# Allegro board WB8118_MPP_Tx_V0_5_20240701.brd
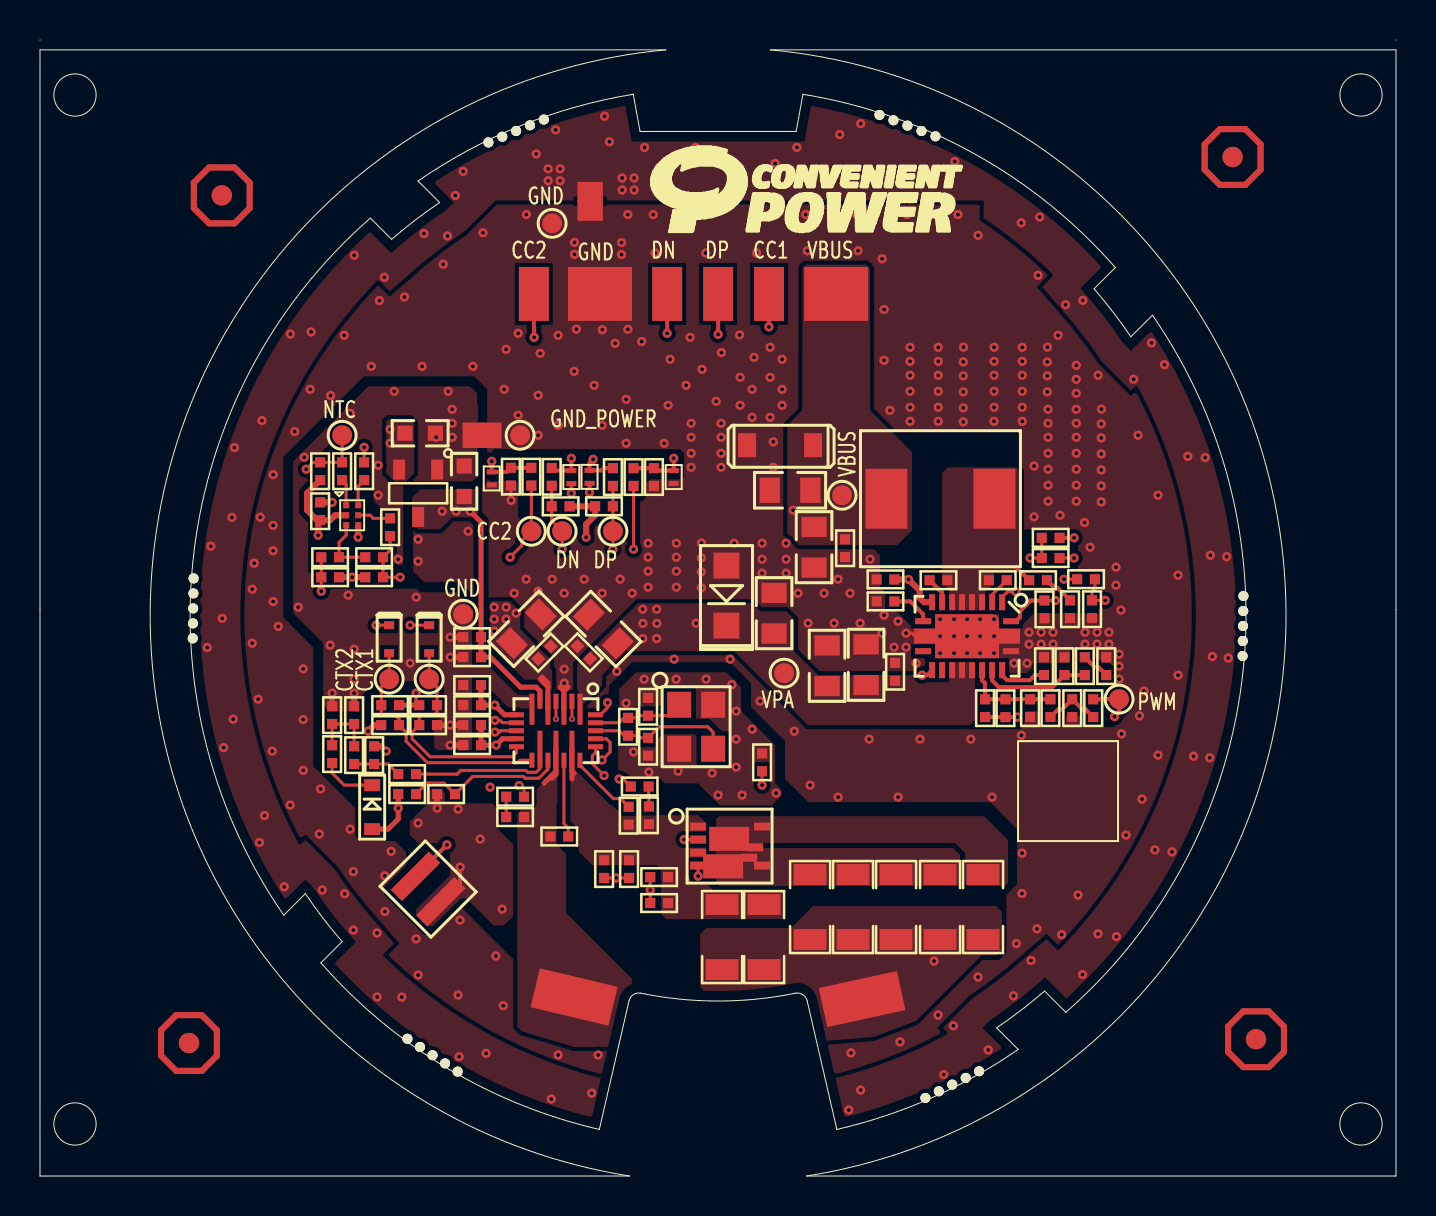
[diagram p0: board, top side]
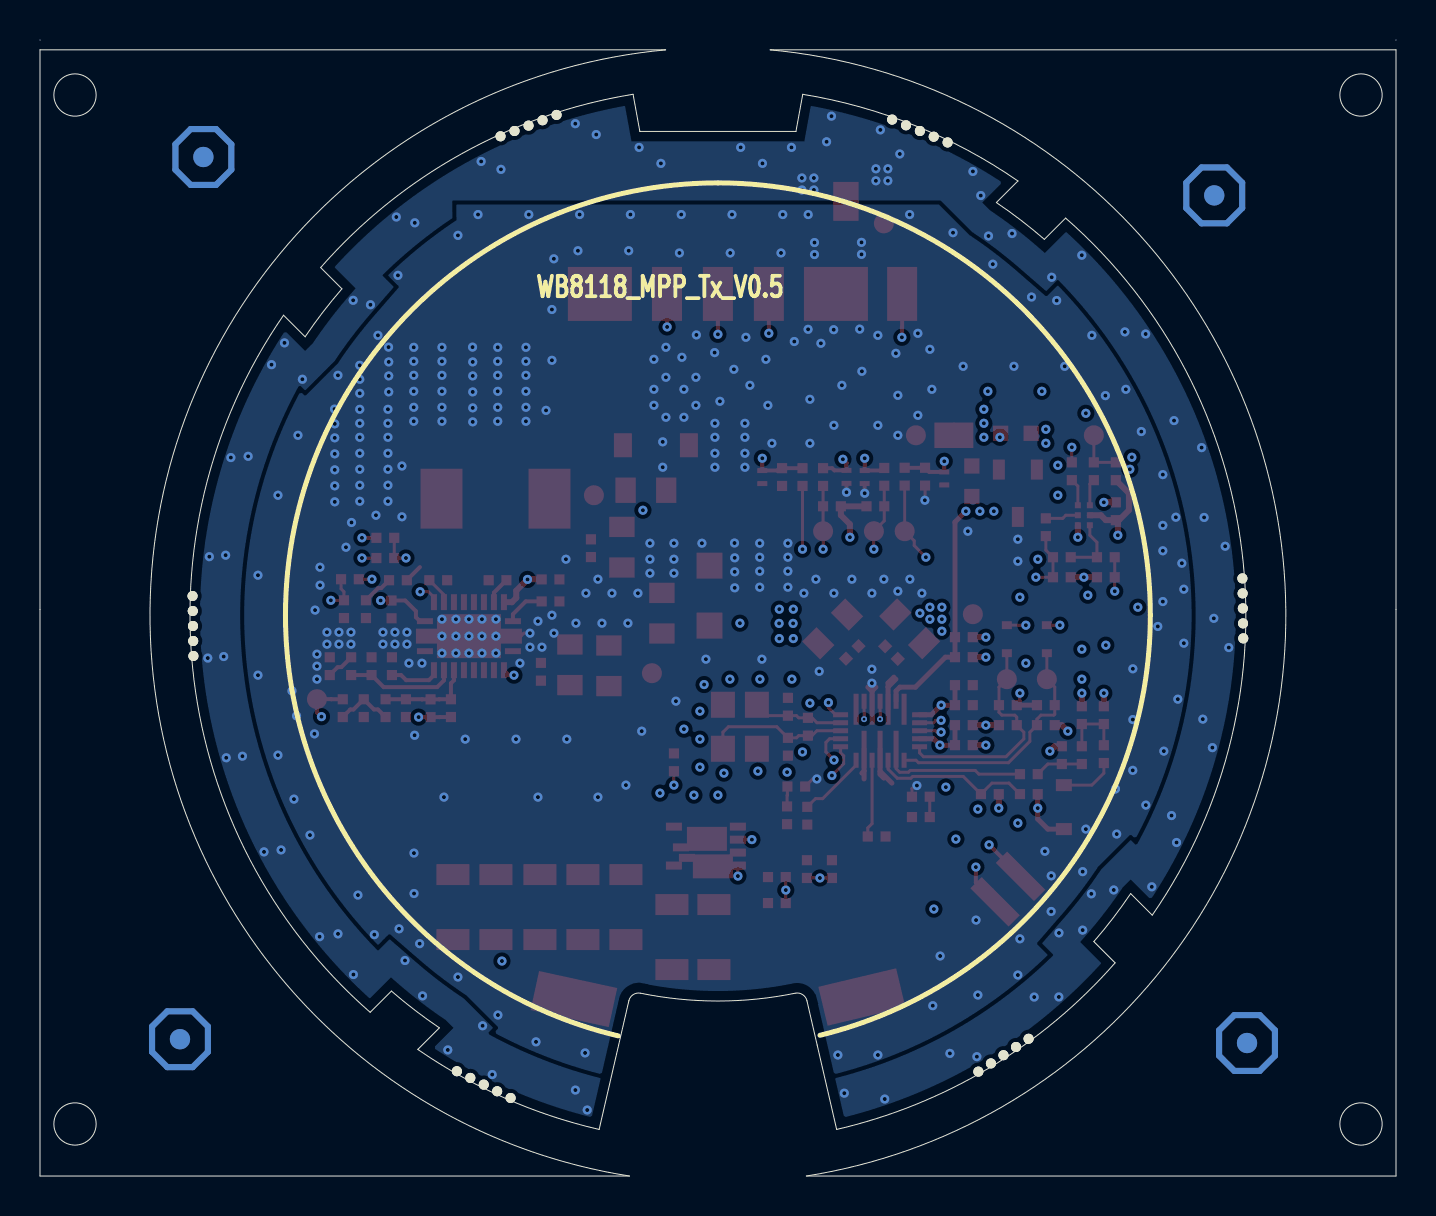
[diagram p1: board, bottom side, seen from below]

Outline 67.81 x 56.83 mm; copper layers: TOP, L2_GND, L3_PWR, BOTTOM. Coordinates in mm from the lower left corner of the outline.
Outline path: circle c1.75,54.07 r1.06 ; circle c1.75,2.6 r1.06 ; circle c66.06,54.07 r1.06 ; circle c66.06,2.6 r1.06 ; 0,56.82 0,56.83 ; 67.81,56.83 67.81,56.82 ; 0,56.33 0,0 29.49,0 arc(5.52,28.97) 31.3,56.33 0,56.33 ; 12.19,13.05 13.27,14.13 arc(14.15,12.9) 15.11,11.73 14.05,10.66 arc(20.35,5.4) 27.97,2.33 28.94,6.55 29.46,8.77 arc(29.67,9.08) 30.04,9.14 arc(33.91,8.75) 37.78,9.14 arc(38.15,9.08) 38.36,8.77 39.85,2.33 arc(44.57,3.9) 48.92,6.33 47.84,7.41 arc(49.06,8.3) 50.24,9.25 51.3,8.19 arc(60.11,24.8) 55.63,43.06 54.55,41.98 arc(53.67,43.21) 52.71,44.38 53.77,45.44 arc(46.72,51.14) 38.15,54.11 37.81,52.25 30.01,52.25 29.67,54.11 arc(24.04,52.54) 18.9,49.77 19.98,48.69 arc(18.76,47.81) 17.58,46.85 16.52,47.92 arc(7.71,31.31) 12.19,13.05 ; 36.52,56.33 arc(62.3,28.97) 38.33,0 67.81,0 67.81,56.33 36.52,56.33

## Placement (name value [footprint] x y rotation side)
C1  1000pF  [C0402]  51.51 28.35 90 top
C2  0.1uF  [C0402]  44.93 29.8 180 top
C5  0.1uF  [C0402]  40.26 31.4 270 top
C6  22uF  [C0805]  38.71 31.45 270 top
C7  22uF  [C0805]  37.51 34.3 180 top
C8  0.1uF  [C0402]  42.76 25.22 90 top
C10  22uF  [C0805]  41.31 25.57 90 top
C11  22uF  [C0805]  39.36 25.52 90 top
C12  22uF  [C0805]  36.71 28.15 90 top
C14  33pF  [C0402]  47.26 23.4 90 top
C15  1uF  [C0402]  50.23 28.34 270 top
C17  0.01uF  [C0402]  51.62 23.4 90 top
C21  4700pF  [C0402]  29.99 19.48 180 top
C22  0.1uF  [C1206]  38.51 13.45 270 top
C23  22uF  [C0805]  24.32 27.37 45 top
C24  0.1uF  [C1206]  40.66 13.45 270 top
C25  0.1uF  [C0402]  29.44 18.02 270 top
C26  0.022uF  [C0402]  30.96 14.95 180 top
C27  4700pF  [C0402]  23.76 18.97 180 top
C28  0.1uF  [C1206]  42.81 13.45 270 top
C29  2.2uF  [C0402]  21.61 25.95 180 top
C30  0.1uF  [C0402]  21.61 26.95 180 top
C32  0.1uF  [C1206]  45.01 13.45 270 top
C33  0.1uF  [C0402]  27.19 26.19 135 top
C34  22uF  [C0805]  28.17 27.36 135 top
C35  0.1uF  [C0402]  25.23 26.18 45 top
C36  0.1uF  [C0402]  25.97 16.98 180 top
C37  15pF  [C0402]  30.41 21.47 90 top
C38  0.047uF  [C1206]  47.16 13.45 90 top
C39  0.022uF  [C0402]  28.21 15.35 270 top
C40  0.022uF  [C0402]  18.36 20.1 180 top
C41  15pF  [C0402]  30.41 23.47 270 top
C42  2.2uF  [C0402]  21.61 23.55 180 top
C43  0.1uF  [C0402]  21.61 24.55 180 top
C44  2.2uF  [C0402]  21.61 22.55 180 top
C45  0.1uF  [C0402]  21.61 21.55 180 top
C46  0.01uF  [C0402]  16.71 21.05 90 top
C47  0.01uF  [C0402]  15.71 23.05 90 top
C48  0.022uF  [C1206]  36.21 11.95 270 top
C49  0.033uF  [C1206]  34.11 11.95 270 top
C51  0.01uF  [C0402]  42.28 28.74 0 top
C52  0.01uF  [C0402]  53.32 25.5 270 top
C54  1uF  [C0402]  42.28 29.84 180 top
C55  33pF  [C0402]  51.23 25.5 90 top
C56  10uF  [C0603]  21.21 34.75 90 top
C57  0.1uF  [C0402]  14.01 33.25 90 top
C58  10uF  [C0603]  19.01 37.15 0 top
D1  -  [SMF12CA]  37.01 36.55 180 top
D2  5V  [SMD-2-X0_6Y0_55-0_85-B]  31.69 34.96 90 top
D3  5V  [SMD-2-X0_6Y0_55-0_85-B]  22.59 34.89 90 top
D4  5V  [SMD-2-X0_6Y0_55-0_85-B]  27.48 34.97 90 top
D5  5V  [SMD-2-X0_6Y0_55-0_85-B]  26.57 34.96 90 top
D6  1N4148WT  [SOD523-2-X0_6Y0_7-1_42]  19.46 26.85 270 top
D7  1N4148WS  [SOD323]  16.61 18.45 270 top
D8  1N4148WT  [SOD523-2-X0_6Y0_7-1_42]  17.46 26.85 270 top
D9  -  [SMF15CA]  34.33 29.03 90 top
J1  CON7  [SMD-6-MPP-TX1]  32.64 44.12 0 top
L1  2.2uH  [CMLO0620]  45.03 33.88 0 top
NOREF  -  [unnamed]  23.05 54.12 202.4 top
NOREF#2  -  [unnamed#2]  7.45 6.65 0 top
NOREF#3  -  [unnamed]  5.66 28.42 269.2 top
NOREF#4  -  [unnamed]  18.54 4.37 326.8 top
NOREF#5  -  [unnamed#2]  59.64 50.97 0 top
NOREF#6  -  [#3]  36.52 56.33 0 top
NOREF#7  -  [#3]  38.33 0 0 top
NOREF#8  -  [unnamed#2]  9.09 49.05 0 top
NOREF#9  -  [unnamed]  46.51 2.78 26.5 top
NOREF#10  -  [unnamed]  62.16 27.48 89.2 top
NOREF#11  -  [#3]  0 56.33 0 top
NOREF#12  -  [#3]  0 56.82 0 top
NOREF#13  -  [#3]  0 0 90 top
NOREF#14  -  [#3]  0 0 0 top
NOREF#15  -  [unnamed#4]  44.09 54.41 159.1 top
NOREF#16  -  [unnamed#2]  60.81 6.84 0 top
NOREF#17  -  [unnamed#2]  60.81 6.84 180 bottom
NOREF#18  -  [unnamed#2]  9.09 49.05 180 bottom
NOREF#19  -  [unnamed#2]  7.45 6.65 180 bottom
NOREF#20  -  [unnamed#2]  59.64 50.97 180 bottom
NTC1  10K  [SMD-2-X0_8Y2_7-1_8]  19.41 14.35 315 top
NTC2  10K  [R0402]  36.11 20.69 90 top
P1+1  VCOIL  [TP-SMD-X2Y3]  41.11 8.85 102.3 top
P1+2  SW1  [TP-SMD-X2Y3]  26.71 8.95 76.6 top
Q2  -  [AD60K45D3]  34.51 16.5 90 top
R4  1  [R0402]  49.91 29.8 180 top
R6  22  [R0402]  29.68 34.96 270 top
R7  22  [R0402]  24.57 34.98 270 top
R9  22  [R0402]  28.65 34.96 270 top
R10  33K  [R0402]  50.54 31.92 0 top
R11  22  [R0402]  25.59 34.97 270 top
R12  5.1K  [R0402]  30.7 34.96 270 top
R13  5.1K  [R0402]  23.55 34.98 270 top
R14  39K  [R0402]  50.53 23.4 270 top
R15  100K  [R0402]  52.67 23.4 90 top
R19  39K  [R0402]  49.51 23.4 270 top
R20  33K  [R0402]  50.54 30.91 180 top
R24  1  [R0402]  30.45 18.04 90 top
R25  3.3K  [R0402]  14.01 35.25 270 top
R27  51K  [R0402]  30.96 13.65 180 top
R31  1  [R0402]  23.76 17.95 0 top
R34  33K  [R0402]  18.36 19.1 180 top
R35  16K  [R0402]  20.31 19.1 0 top
R38  51K  [R0402]  29.46 15.35 270 top
R39  1M  [R0402]  29.41 22.47 270 top
R40  3.3K  [R0402]  15.71 21.05 90 top
R41  1.5K  [R0402]  14.61 21.1 90 top
R43  33K  [R0402]  14.61 23.05 90 top
R46  3.3K  [R0402]  26.03 33.5 0 top
R47  3.3K  [R0402]  28.21 33.5 180 top
R49  430K  [R0402]  47.89 29.8 0 top
R50  100K  [R0402]  52.61 28.35 90 top
R51  100K  [R0402]  52.31 29.85 180 top
R52  374K  [R0402]  48.28 23.4 90 top
R53  150K  [R0402]  50.21 25.5 90 top
R54  33K  [R0402]  52.25 25.5 270 top
R55  3.3K  [R0402]  14.51 29.95 0 top
R56  240  [R0402]  15.11 35.25 270 top
R57  240  [R0402]  14.51 30.95 0 top
R58  240  [R0402]  16.21 35.25 270 top
R59  0  [R0402]  16.71 30.95 0 top
R60  0  [R0402]  17.51 32.45 270 top
R61  3.3K  [R0402]  16.71 29.95 180 top
R62  1K  [R0402]  19.41 23.55 0 top
R63  1K  [R0402]  17.51 23.55 180 top
R64  100K  [R0402]  19.41 22.55 0 top
R65  100K  [R0402]  17.51 22.55 180 top
RE1  GND_TIE  [TE0805]  22.11 37.05 0 top
RE2  GND_TIE2  [TE0805]  27.51 48.75 270 top
TP_CTX1  TPDRI  [TP-SMD-CIR1]  19.46 24.85 180 top
TP_CTX2  TPDRI  [TP-SMD-CIR1]  17.46 24.85 0 top
TP_GND1  TPDRI  [TP-SMD-CIR1]  25.61 47.65 0 top
TP_GP1  TPDRI  [TP-SMD-CIR1]  24.01 37.05 0 top
TP_GS1  TPDRI  [TP-SMD-CIR1]  21.16 28.1 0 top
TP_NTC_COIL1  TPDRI  [TP-SMD-CIR1]  15.11 37.05 180 top
TP_PWM_DUTY1  TPDRI  [TP-SMD-CIR1]  53.96 23.85 0 top
TP_SCL0_DP1  TPDRI  [TP-SMD-CIR1]  28.65 32.25 0 top
TP_SDA0_DN1  TPDRI  [TP-SMD-CIR1]  26.11 32.25 0 top
TP_VBUS1  TPDRI  [TP-SMD-CIR1]  40.11 34.05 0 top
TP_VPA1  TPDRI  [TP-SMD-CIR1]  37.21 25.15 0 top
TP_YUART_TXD1  TPDRI  [TP-SMD-CIR1]  24.57 32.25 0 top
U2  -  [SCT12A2]  46.36 27 180 top
U3  WB8118  [FCQFN24L]  25.8 22.27 270 top
U4  ME6209A33  [SOT23-3]  18.91 34.15 180 top
U5  T91-406  [DS4301]  15.61 33.05 0 top
Y1  40.0000MHZ  [SMD-4-2_2-1_7]  32.81 22.47 270 top

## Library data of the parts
C1 C2 C5-C8 C10-C12 C14 C15 C17 C21-C30 C32-C49 C51 C52 C54-C58 = C-2P-SMD
D1-D5 D9 = TVS_BI_2PIN
D6-D8 NTC1 = STANDARD_2PIN
J1 = CON7_0
L1 = STANDARD_IND_2PIN
NTC2 = SMD_1
P1+1 P1+2 = HOLE-2_5
Q2 = VS3622DE_2
R4 R6 R7 R9-R15 R19 R20 R24 R25 R27 R31 R34 R35 R38-R41 R43 R46 R47 R49-R65 = R-2P-SMD
RE1 RE2 = GND TIE
TP_CTX1 TP_CTX2 TP_GND1 TP_GP1 TP_GS1 TP_NTC_COIL1 TP_PWM_DUTY1 TP_SCL0_DP1 TP_SDA0_DN1 TP_VBUS1 TP_VPA1 TP_YUART_TXD1 = TPSMD
U2 = JW5513_2
U3 = CPS8602
U4 = ME6209A40
U5 = SLS32AIA020X2_0
Y1 = REVERSE_4PIN_1-4PIN_4VCC_3

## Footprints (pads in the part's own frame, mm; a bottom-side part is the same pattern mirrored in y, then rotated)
AD60K45D3
  rect 0.4x0.8 smd: 1(0.975,1.6) 2(0.325,1.6) 3(-0.325,1.6) 4(-0.975,1.6) 5(-0.975,-1.6) 8(0.975,-1.6)
  custom 0.306x0.306 smd: 6(-1,0) 7(0.35,-0.3)
C0402
  rect 0.508x0.508 smd: 1(-0.445,0) 2(0.445,0)
C0603
  rect 0.762x0.762 smd: 1(-0.762,0) 2(0.762,0)
C0805
  rect 1.016x1.27 smd: 1(-1.016,0) 2(1.016,0)
C1206
  rect 1.049x1.651 smd: 1(-1.625,0) 2(1.625,0)
CMLO0620
  rect 2.1x3 smd: 1(-2.7,0) 2(2.7,0)
DS4301
  rect 0.3x0.3 smd: 1(-0.3,0.5) 2(-0.3,0) 3(-0.3,-0.5) 4(0.3,-0.5) 5(0.3,0) 6(0.3,0.5)
FCQFN24L
  rect 1.55x0.25 smd: 1(-1.075,1.2) 3(-1.075,0.4) 5(-1.075,-0.4) 7(-1.075,-1.2)
  rect 0.75x0.25 smd: 2(-1.475,0.8) 4(-1.475,0) 6(-1.475,-0.8) 13(1.475,-1.2) 15(1.475,-0.4) 17(1.475,0.4) 19(1.475,1.2)
  rect 0.25x0.75 smd: 8(-0.8,-1.975) 9(-0.4,-1.975) 10(0,-1.975) 11(0.4,-1.975) 12(0.8,-1.975) 20(0.8,1.975) 21(0.4,1.975) 22(0,1.975) 23(-0.4,1.975) 24(-0.8,1.975)
  rect 1.85x0.25 smd: 14(0.925,-0.8) 16(0.925,0) 18(0.925,0.8)
R0402
  rect 0.508x0.508 smd: 1(-0.445,0) 2(0.445,0)
SCT12A2
  rect 0.8x0.3 smd: 1(-2.2,-0.75) 10(2.2,-0.75) 11(2.2,0.75) 20(-2.2,0.75)
  rect 0.3x0.8 smd: 2(-1.75,-1.7) 3(-1.25,-1.7) 4(-0.75,-1.7) 5(-0.25,-1.7) 6(0.25,-1.7) 7(0.75,-1.7) 8(1.25,-1.7) 9(1.75,-1.7) 12(1.75,1.7) 13(1.25,1.7) 14(0.75,1.7) 15(0.25,1.7) 16(-0.25,1.7) 17(-0.75,1.7) 18(-1.25,1.7) 19(-1.75,1.7)
  custom 0.55x0.55 smd: 21(0,0)
SMD-2-X0_6Y0_55-0_85-B
  rect 0.25x0.5 smd: 1(-0.325,0) 2(0.325,0)
SMD-2-X0_8Y2_7-1_8
  rect 0.8x2.7 smd: 1(-0.9,0) 2(0.9,0)
SMD-4-2_2-1_7
  rect 1.3x1.199 smd: 1(-1.1,-0.85) 2(1.1,-0.85) 3(1.1,0.85) 4(-1.1,0.85)
SMD-6-MPP-TX1
  rect 3.2x2.7 smd: 1(7.176,0) 6(-4.632,0)
  rect 1.5x2.7 smd: 2(3.819,0) 3(-7.942,0) 4(1.272,0) 5(-1.275,0)
SMF12CA
  rect 0.9x1.2 smd: 1(-1.65,0) 2(1.65,0)
SMF15CA
  rect 1.3x1.3 smd: 1(-1.5,0) 2(1.5,0)
SOD323
  rect 0.6x0.8 smd: 1(-1.1,0) 2(1.1,0)
SOD523-2-X0_6Y0_7-1_42
  rect 0.4x0.5 smd: 1(-0.7,0) 2(0.7,0)
SOT23-3
  rect 0.6x1 smd: 1(-0.95,-1.185) 2(0.95,-1.185) 3(0,1.185)
TE0805
  rect 1.016x1.27 smd: 1(-0.466,0) 2(0.466,0)
TP-SMD-CIR1
  round 1 smd: 1(0,0)
TP-SMD-X2Y3
  rect 2x4 smd: 1(0,0)
unnamed
  round 0.5 hole 0.5 unplated: (-1.5,2) (-0.75,2) (0,2) (0.75,2) (1.5,2)
unnamed#2
  round 1.016 smd: 1(0,0)
unnamed#4
  round 0.5 hole 0.5 unplated: (-1.5,2) (-0.75,2) (0,2) (0.75,2) (1.5,2)

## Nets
GND_IN: RE2.1
GND_POWER: C1.1 C5.2 C6.2 C7.2 C8.2 C10.2 C11.2 C12.2 C15.2 C17.1 C21.2 C23.2 C27.1 C33.2 C34.2 C35.2 C51.1 C52.1 C54.2 C55.2 D1.2 D2.1 D3.1 D4.1 D5.1 D9.2 J1.6(GND) R12.2 R13.2 R19.2 R50.1 R53.2 RE1.2 RE2.2 TP_GND1.1 TP_GP1.1 U2.20(AGND) U2.21(PGND) U3.3(PGND)
GND_SIG: C29.2 C30.2 C37.1 C41.1 C42.2 C43.2 C44.2 C45.2 C46.2 C47.2 C56.2 C57.2 C58.2 NTC1.2 NTC2.2 R35.1 R43.2 R64.2 R65.2 RE1.1 TP_GS1.1 U3.7(GND) U4.1(VSS) U5.4(VSS) Y1.2(NC2) Y1.4(NC1)
VBUS: C5.1 C6.1 C7.1 C29.1 C30.1 C54.1 C56.1 D1.1 J1.1(VBUS) L1.1 R10.2 TP_VBUS1.1 U2.9(VIN) U3.6(VIN) U4.3(VIN)
BOOST_BST: C2.2 U2.8(BOOT)
BOOST_FB: C14.2 R14.1 R19.1 R52.2 U2.17(FB)
BOOST_PWM: R15.2 TP_PWM_DUTY1.1 U3.24(TXD1/PWMBP/GP6/LED0/AIN7)
CC1: R6.2 U3.2(CC1/GP0/AIN0)
CC1_IN: D2.2 J1.2(CC1) R6.1 R12.1
CC2: R7.2 TP_YUART_TXD1.1 U3.4(CC2/GP1/AIN1)
CC2_IN: D3.2 J1.3(CC2) R7.1 R13.1
COMM: C40.1 U3.14(COMM/AIN8)
COMM_IN: C40.2 C46.1 R40.1
COMP: C55.1 R54.2 U2.18(COMP)
COMP_R: C52.2 R54.1
DN_IN: D5.2 J1.5(DN) R11.1
DP_IN: D4.2 J1.4(DP) R9.1
DUTY_CTRL: C17.2 R14.2 R15.1
EASK_D: D7.1(K) R41.1
ENV_RC: C47.1 R40.2 R41.2 R43.1
FOD: R34.1 R35.2 U3.15(FOD)
FSW: R49.2 U2.3(FSW)
GP0: R60.1 U5.5(GPO)
GP1: R20.1 R59.2 R60.2 R61.1
ILMT: R53.1 U2.19(ILMT)
LDO1P8: C44.1 C45.1 R46.2 R47.2 U3.11(DVDD)
LDO3P3: C57.1 C58.1 R25.2 R55.2 R61.2 U4.2(VOUT) U5.2(VCC)
LDO4P5: C42.1 C43.1 R62.1 R63.1 U3.8(LDO4P5)
NTC_MPP: NTC1.1 NTC2.1 R25.1 R56.1 TP_NTC_COIL1.1 U3.20(LED0/PWMBN/GP2/AIN4/SDA1)
SCL0_DP: R9.2 R47.1 TP_SCL0_DP1.1 U3.10(SCL0/DP/OD1/RXD0/AIN3)
SCL1: R55.1 R57.1 R58.1 U3.21(LED1/RXD1/GP3/NTC/SCL1)
SCL1_1: R57.2 R59.1 U5.3(SCL)
SCL1_2: R58.2 U5.6(RFU)
SCT_EN: R10.1 R20.2 U2.2(EN)
SCT_MODE: R50.2 R51.1 U2.12(MODE)
SCT_SS: C51.2 U2.10(SS)
SCT_VCC: C15.1 R51.2 U2.1(VCC)
SDA0_DN: R11.2 R46.1 TP_SDA0_DN1.1 U3.9(SDA0/DN/OD0/TXD0/AIN2)
SDA1_1: R56.2 U5.1(SWI/SDA)
SW: C2.1 L1.2 R4.2 R49.1 U2.4(SW#4) U2.5(SW#5) U2.6(SW#6) U2.7(SW#7)
SW1: C36.2 P1+2.1 R31.2 U3.16(SW1)
SW1_RC: C27.2 R31.1
SW2: C25.2 C26.1 C39.1 C48.1 C49.1 Q2.1(S1) Q2.3(S2) R24.1 R27.1 R38.1 U3.18(SW2)
SW2_RC: C21.1 R24.2
SW_CTX2: D8.2(A) R63.2 R65.1 TP_CTX2.1 U3.13(SCL1/OD3/SNSN)
SW_CTX3: D6.2(A) R62.2 R64.1 TP_CTX1.1 U3.12(SDA1/OD2/SNSP)
SW_D1: C38.2 Q2.7(D1#7) Q2.8(D1#8)
SW_D2: C22.1 C24.1 C28.1 C32.1 Q2.5(D2#5) Q2.6(D2#6)
SW_RC: C1.2 R4.1
SWITCH_G1: C39.2 D8.1(K) Q2.2(G1) R38.2
SWITCH_G2: C26.2 D6.1(K) Q2.4(G2) R27.2
TX_BST1: C36.1 U3.17(BST1)
TX_BST2: C25.1 U3.19(BST2)
VCOIL: C22.2 C24.2 C28.2 C32.2 C38.1 C48.2 C49.2 D7.2(A) P1+1.1 R34.2
VPA: C8.1 C10.1 C11.1 C12.1 C14.1 C23.1 C33.1 C34.1 C35.1 D9.1 R52.1 TP_VPA1.1 U2.14(OUT#14) U2.15(OUT#15) U2.16(OUT#16) U3.1(PVIN1) U3.5(PVIN2)
XTAL_IN: C37.2 R39.2 U3.22(XTAL_IN/GP4/AIN5) Y1.3(XTAL2)
XTAL_OUT: C41.2 R39.1 U3.23(XTAL_OUT/GP5/AIN6) Y1.1(XTAL1)

Pads without a net: NOREF#2 1; NOREF#5 1; NOREF#8 1; NOREF#16 1; NOREF#17 1; NOREF#18 1; NOREF#19 1; NOREF#20 1; U2 11 13

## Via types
v1: diameter 0.457, hole 0.203, TOP to BOTTOM, 495 vias
v2: diameter 0.3, hole 0.15, TOP to BOTTOM, 2 vias

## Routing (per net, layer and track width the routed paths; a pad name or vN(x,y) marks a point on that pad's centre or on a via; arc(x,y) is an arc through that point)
GND_IN:
  vias: v1(8.36,26.43) v1(8.54,31.5) v1(9.11,27.9) v1(9.18,21.43) v1(9.6,32.94) v1(9.72,36.44) v1(9.66,22.85) v1(10.97,16.68) v1(11.1,37.79) v1(11.23,18.03) v1(12.21,14.47) v1(12.52,42.12) v1(13.56,42.22) v1(14.11,14.31) v1(15.24,14.12) v1(15.71,46.06) v1(15.67,12.3) v1(16.85,12.16) v1(16.86,8.96) v1(17.22,44.96) v1(18.09,8.95) v1(19.2,47.14) v1(20.38,47.02) v1(20.76,49.04) v1(20.96,5.97) v1(21.16,50.25) v1(22.31,6.13) v1(24.81,51.12) v1(25.41,50.38) v1(25.41,49.78) v1(25.57,3.85) v1(25.79,52.33) v1(26.01,50.38) v1(26.01,49.78) v1(27.59,4.14) v1(28.23,53.02) v1(28.47,51.73) v1(29.11,49.92) v1(29.11,49.32) v1(29.71,49.92) v1(29.71,49.32) v1(30.23,51.45) v1(31.68,50.65) v1(32.77,51.45) v1(36.76,50.65) v1(37.85,51.45) v1(40,52.1) v1(40.45,3.3) v1(41.04,52.64) v1(41.04,4.3) v1(44.76,50.35) v1(45.2,5.08) v1(45.75,50.75) v1(45.68,7.51) v1(47.42,6.31) v1(48.68,9.01) v1(49.07,47.68) v1(49.56,10.78) v1(49.99,47.97) v1(51.29,43.58) v1(52.15,43.81) v1(52.14,10.08) v1(52.91,12.11) v1(53.83,11.97) v1(54.69,39.86) v1(55.58,41.68) v1(55.75,16.31) v1(56.23,40.58) v1(56.61,16.21) v1(57.4,36) v1(57.69,21) v1(58.27,35.94) v1(58.53,31.06) v1(58.5,20.92) v1(58.62,25.98) v1(59.34,30.98) v1(59.42,25.91)
GND_POWER: length 8.2
  TOP w0.15: v1(23.96,19.53) 24.05,19.53 24.2,19.38 C27.1 ; v1(28.96,19.86) 29.17,19.86 C21.2 ; v1(46.36,27) v1(45.71,27) v1(45.01,27) 43.76,27 43.61,27.15 v1(43.31,27.15) ; 26.2,23.25 U3.3 ; v1(23.56,33.8) 23.55,33.81 R13.2
  TOP w0.2: D4.1 v1(27.48,34.2) ; D5.1 v1(26.57,34.15)
  TOP w0.25: 26.2,24.24 U3.3 ; 26.2,24.24 26.41,24.45 ; 26.2,24.24 26.2,24.26 ; 26.01,24.45 26.2,24.26 ; 26.2,24.26 26.2,24.34 26.21,24.35 v1(26.21,24.65)
  vias: v1(10.61,29.35) v1(10.61,26.65) v1(10.71,30.65) v1(10.91,23.85) v1(11.01,32.95) v1(11.61,21.25) v1(11.66,35.09) v1(11.66,32.55) v1(11.66,31.28) v1(11.66,28.74) v1(11.91,27.49) v1(12.51,18.55) v1(12.74,37.24) v1(13.16,25.37) v1(13.16,22.83) v1(13.16,20.29) v1(13.51,39.35) v1(14.03,19.36) v1(13.97,17.11) v1(14.53,39.04) v1(15.21,42.05) v1(15.51,17.35) v1(15.67,15.22) v1(16.57,40.5) v1(16.97,43.79) v1(17.24,15.01) v1(17.24,13.23) v1(17.56,16.24) v1(18.23,43.97) v1(18.81,11.86) v1(18.91,31.85) v1(18.91,30.75) v1(18.91,10.05) v1(19.11,40.5) v1(20.16,45.61) v1(20.91,9.05) v1(21,12.8) v1(21.41,32.25) v1(21.65,40.5) v1(22.15,47.19) v1(22.8,11.01) v1(23.21,39.35) v1(23.16,8.52) v1(23.31,41.35) v1(23.71,29.15) v1(23.91,42.15) v1(23.91,38.05) v1(24.32,48.09) v1(24.31,29.85) v1(24.91,39.05) v1(24.91,37.05) v1(24.91,29.25) v1(25.01,41.15) v1(25.61,29.85) v1(25.91,42.05) v1(25.91,37.55) v1(25.91,6.05) v1(26.21,29.15) v1(26.21,25.35) v1(26.73,46.7) v1(26.73,46.1) v1(26.71,40.25) v1(26.82,42.36) v1(27.21,29.85) v1(27.71,39.55) v1(27.91,6.05) v1(28.12,42.33) v1(28.11,37.55) v1(28.11,29.15) v1(28.76,41.65) v1(28.84,25.25) v1(29.01,29.85) v1(29.08,46.69) v1(29.08,46.09) v1(29.31,38.85) v1(29.31,36.65) v1(29.4,48.09) v1(29.4,42.35) v1(29.61,29.15) v1(30.09,41.74) v1(30.41,31.65) v1(30.41,30.95) v1(30.41,30.25) v1(30.41,29.45) v1(30.67,48.09) v1(30.75,46.17) v1(31.21,36.65) v1(31.41,38.55) v1(31.51,40.85) v1(31.71,25.85) v1(31.82,31.65) v1(31.82,30.95) v1(31.82,30.25) v1(31.82,29.45) v1(32.31,39.55) v1(32.51,41.95) v1(32.56,37.65) v1(32.56,36.95) v1(32.56,36.15) v1(32.56,35.45) v1(33.11,40.35) v1(33.08,31.66) v1(33.07,30.92) v1(33.07,30.22) v1(33.07,29.42) v1(33.21,48.09) v1(33.29,46.17) v1(33.81,38.75) v1(34.06,37.65) v1(34.06,36.95) v1(34.06,36.15) v1(34.06,35.45) v1(34.07,41.19) v1(34.51,25.85) v1(34.71,31.65) v1(34.99,42.07) v1(35.01,39.95) v1(35.01,38.55) v1(35.61,39.35) v1(35.61,37.95) v1(35.75,48.09) v1(35.71,40.95) v1(35.83,46.17) v1(36.01,23.75) v1(36.11,31.65) v1(36.11,30.85) v1(36.11,30.15) v1(36.51,41.45) v1(36.51,39.95) v1(36.51,37.95) v1(36.67,36.72) v1(36.67,35.45) v1(37.11,40.85) v1(37.11,39.35) v1(37.11,38.55) v1(37.31,31.65) v1(37.31,30.85) v1(37.31,30.15) v1(37.72,22.25) v1(37.91,29.15) v1(38.29,48.09) v1(38.37,46.28) v1(38.41,27.65) v1(38.51,19.55) v1(39.21,29.15) v1(39.71,27.65) v1(39.91,29.85) v1(39.91,18.95) v1(40.51,29.15) v1(40.55,6.16) v1(40.83,48.09) v1(40.91,46.28) v1(41.01,27.65) v1(41.51,30.85) v1(41.47,21.85) v1(42.11,45.88) v1(42.11,27.15) v1(42.21,43.34) v1(42.21,40.8) v1(42.21,28.05) v1(42.5,38.3) v1(42.71,26.45) v1(42.91,27.75) v1(42.91,18.95) v1(43.01,6.71) v1(43.31,26.45) v1(43.37,48.09) v1(43.51,41.45) v1(43.51,40.75) v1(43.51,40.05) v1(43.51,39.25) v1(43.51,38.45) v1(43.51,37.75) v1(43.81,25.65) v1(44.01,21.85) v1(44.92,41.45) v1(44.92,40.75) v1(44.92,40.05) v1(44.92,39.25) v1(44.92,38.45) v1(44.92,37.75) v1(44.91,8.05) v1(45.01,27.85) v1(45.01,26.15) v1(45.71,27.85) v1(45.71,26.15) v1(45.91,48.09) v1(46.18,41.46) v1(46.17,40.72) v1(46.17,40.02) v1(46.17,39.22) v1(46.17,38.42) v1(46.17,37.72) v1(46.36,27.85) v1(46.36,26.15) v1(46.55,21.85) v1(46.91,47.05) v1(46.91,9.95) v1(47.01,27.85) v1(47.01,27) v1(47.01,26.15) v1(47.61,18.95) v1(47.71,41.45) v1(47.71,40.75) v1(47.71,40.05) v1(47.71,39.25) v1(47.71,38.45) v1(47.71,37.75) v1(47.71,27.85) v1(47.71,27) v1(47.71,26.15) v1(48.71,25.65) v1(48.82,11.62) v1(49.12,41.45) v1(49.12,40.75) v1(49.12,40.05) v1(49.12,39.25) v1(49.12,38.45) v1(49.12,37.75) v1(49.08,22.05) v1(49.11,16.15) v1(49.11,14.13) v1(49.36,25.65) v1(49.46,27.2) v1(49.46,26.6) v1(49.71,35.52) v1(49.71,32.98) v1(49.86,12.37) v1(49.91,45.05) v1(50.06,27.2) v1(50.06,26.6) v1(50.38,41.46) v1(50.37,40.72) v1(50.37,40.02) v1(50.37,39.22) v1(50.41,38.35) v1(50.41,37.65) v1(50.41,36.95) v1(50.41,36.15) v1(50.41,35.35) v1(50.41,34.55) v1(50.41,33.75) v1(50.66,27.2) v1(50.66,26.6) v1(50.91,42.05) v1(51.01,33.05) v1(51.09,12.07) v1(51.82,40.55) v1(51.82,39.85) v1(51.82,39.15) v1(51.82,38.35) v1(51.82,37.65) v1(51.82,36.95) v1(51.82,36.15) v1(51.82,35.35) v1(51.82,34.55) v1(51.82,33.75) v1(51.91,14.05) v1(52.23,32.69) v1(52.26,27.2) v1(52.26,26.6) v1(52.51,31.45) v1(52.86,27.2) v1(52.86,26.6) v1(52.91,40.05) v1(53.08,38.36) v1(53.07,37.62) v1(53.07,36.92) v1(53.07,36.12) v1(53.07,35.32) v1(53.07,34.52) v1(53.07,33.72) v1(53.46,27.2) v1(53.46,26.6) v1(53.81,30.45) v1(53.81,29.55) v1(54.05,28.31) v1(53.96,26.1) v1(53.96,25.5) v1(53.96,24.85) v1(54.09,22.12) v1(54.31,17.05) v1(54.91,37.05) v1(54.98,23.02) v1(55.11,18.85) v1(55.21,24.27) v1(55.91,34.05) v1(55.91,21.05) v1(56.91,30.05) v1(56.91,25.05)
GND_SIG: length 10.1
  TOP w0.15: U3.7 24.6,23.36
  TOP w0.2: v1(21.01,15.45) 21.01,14.68 NTC1.2
  TOP w0.3: U5.4 v1(15.91,31.95) ; R43.2 v1(14.61,24.15) ; C30.2 v1(20.51,26.95) ; R35.1 v1(19.87,18.4) ; C47.2 v1(15.71,24.15) ; C44.2 v1(20.51,22.55) R64.2 ; C29.2 v1(20.51,25.95) ; C46.2 17.07,21.5 v1(17.31,21.25) ; v1(16.41,22.25) 16.71,22.55 R65.2 ; C45.2 v1(20.51,21.55) ; v1(14.61,33.7) C57.2
  vias: v1(12.91,28.45) v1(13.21,35.95) v1(14.51,26.55) v1(15.41,29.05) v1(15.51,38.15) v1(15.71,26.35) v1(15.71,24.85) v1(16.91,35.55) v1(16.91,34.05) v1(17.71,39.25) v1(17.91,30.85) v1(18.51,25.65) v1(18.81,28.95) v1(18.91,17.65) v1(19.81,36.95) v1(20.41,39.25) v1(20.61,38.35) v1(20.61,37.65) v1(20.61,36.95) v1(20.91,18.35) v1(22.01,16.85) v1(22.51,19.45) v1(23.11,13.35) v1(29.31,23.65) v1(29.68,21.21) v1(30.21,24.85) v1(30.45,20.2) v1(31.81,24.85) v1(31.91,20.25) v1(33.31,24.85) v1(33.61,20.15) v1(33.91,19.05) v1(34.6,24.58) v1(34.81,23.25) v1(34.81,21.85) v1(34.81,20.45) v1(35.11,19.05) v1(35.61,22.35) v1(36.81,19.15)
VBUS: length 31.6
  TOP w0.2: R10.2 v1(51.71,31.92)
  TOP w0.25: U3.6 25,24.26 24.81,24.45 24.03,24.45 22.53,25.95 C29.1 C30.1 22.05,32.71 v1(21.51,33.25)
  TOP w0.3: C54.1 v1(43.43,29.84) 43.99,29.28 43.99,28.92 44.21,28.7 U2.9
  L3_PWR w0.5: v1(51.71,31.92) 51.37,32.26 49.17,32.26 47.31,30.4 45.35,30.4 44.79,29.84 v1(43.43,29.84) 41.46,29.84 38,33.3 v1(37.66,33.3)
  vias: v1(20.11,33.25) v1(20.81,33.25)
BOOST_BST: length 1.4
  TOP w0.2: C2.2 45.11,29.18 U2.8
BOOST_FB: length 4.8
  TOP w0.2: R14.1 R19.1 48.71,23.85 48.71,23.84 R52.2 47.85,23.84 47.85,23.85 C14.2 47.26,24.65 47.11,24.8 U2.17
BOOST_PWM: length 33.7
  TOP w0.15: U3.24 28.02,23.07 28.38,23.43 v1(28.38,23.68)
  TOP w0.2: v1(53.73,22.98) 53.96,23.2 TP_PWM_DUTY1.1 53.25,23.85 53.24,23.85 R15.2
  L3_PWR w0.15: v1(53.73,22.98) 51.81,21.05 40.51,21.05 35.26,26.31 29.26,26.31 28.38,25.43 v1(28.38,23.68)
CC1: length 20.9
  TOP w0.15: R6.2 v1(29.68,31.35) ; v2(26.6,22.85) U3.2
  L3_PWR w0.15: v2(26.6,22.85) 26,23.45 25.01,23.45 22.11,26.35 22.11,28.55 24.01,30.45 28.78,30.45 v1(29.68,31.35)
CC1_IN: length 12.9
  TOP w0.2: R6.1 R12.1 30.82,35.41 30.94,35.29 D2.2 v1(31.69,35.9) ; J1.2 36.45,44.12 v1(36.45,42.47)
  L3_PWR w0.2: v1(31.69,35.9) 31.69,37.71 v1(36.45,42.47)
CC2: length 15.9
  TOP w0.15: R7.2 TP_YUART_TXD1.1 24.09,31.78 24.09,31.54 v1(23.51,30.95) ; v2(25.8,22.85) U3.4
  L3_PWR w0.15: v2(25.8,22.85) 25.11,22.85 21.71,26.25 21.71,28.6 23.3,30.19 23.3,30.74 v1(23.51,30.95)
CC2_IN: length 11.9
  TOP w0.2: J1.3 24.7,42.47 24.71,42.45 v1(24.71,41.95) ; R7.1 R13.1 23.34,35.22 D3.2 v1(22.59,35.75)
  L3_PWR w0.2: v1(24.71,41.95) 22.59,39.83 v1(22.59,35.75)
COMM: length 7.4
  TOP w0.15: C40.1 20.86,20.1 21.04,20.29 24.29,20.29 24.38,20.2 24.82,20.2 25,20.38 U3.14
COMM_IN: length 2.4
  TOP w0.15: C40.2 17.41,20.61 C46.1 R40.1
COMP: length 5.5
  TOP w0.2: U2.18 47.61,24.79 47.95,24.45 50.62,24.45 C55.1 R54.2
COMP_R: length 1.4
  TOP w0.2: C52.2 52.92,25.45 52.74,25.45 R54.1
DN_IN: length 11.9
  TOP w0.2: R11.1 25.72,35.29 D5.2 v1(26.57,35.9) ; J1.5 v1(31.36,42.15)
  L3_PWR w0.2: v1(31.36,42.15) 26.57,37.36 v1(26.57,35.9)
DP_IN: length 12.7
  TOP w0.2: J1.4 33.91,42.43 v1(33.91,42.1) ; v1(27.66,35.85) 27.48,35.67 D4.2 28.09,35.3 28.2,35.41 R9.1
  L3_PWR w0.2: v1(27.66,35.85) v1(33.91,42.1)
DUTY_CTRL: length 2.9
  TOP w0.2: R14.2 50.91,23.34 51.11,23.34 C17.2 52.13,23.34 52.29,23.34 R15.1
EASK_D: length 2.8
  TOP w0.15: D7.1 15.21,19.55 14.61,20.15 R41.1
ENV_RC: length 3.3
  TOP w0.15: R41.2 R43.1 C47.1 R40.2
FOD: length 8.1
  TOP w0.15: U3.15 25.4,20.36 24.94,19.9 24.26,19.9 24.17,19.99 21.64,19.99 R35.2 20.2,19.65 19.35,19.65 R34.1
FSW: length 1.4
  TOP w0.15: U2.3 47.61,29.07 R49.2
GP0: length 1.7
  TOP w0.15: R60.1 16.67,32.9 16.51,33.05 U5.5
GP1: length 41.3
  TOP w0.15: R20.1 v1(51.71,30.91) ; R60.2 17.51,31.31 R59.2 R61.1 v1(18.01,29.95)
  L3_PWR w0.15: v1(51.71,30.91) 51.17,31.45 49.21,31.45 47.66,29.9 45.76,29.9 45.01,29.15 41.31,29.15 38.14,32.32 28.55,32.32 28.17,32.7 22.69,32.7 19.94,29.95 v1(18.01,29.95)
ILMT: length 2.6
  TOP w0.2: U2.19 48.11,25.05 48.36,24.8 49.5,24.8 49.76,25.06 R53.1
LDO1P8: length 26.6
  TOP w0.25: U3.11 23.13,21.87 v1(22.81,21.55) C45.1 C44.1
  TOP w0.3: R46.2 R47.2 27.76,33.05 27.31,32.6 v1(27.31,31.95)
  L3_PWR w0.5: v1(22.81,21.55) 22.51,21.55 20.89,23.18 18.68,23.18 18.12,23.75 18.12,24.45 18.62,24.95 19.01,24.95 19.81,25.75 19.81,28.4 22.11,30.7 22.11,31.29 23,32.18 26.6,32.18 26.83,31.95 v1(27.31,31.95)
LDO3P3: length 6.1
  TOP w0.3: C57.1 14.51,32.81 14.76,33.05 U5.2 ; C57.1 13.85,32.81 13.36,33.31 13.36,34.15 R25.2 ; C57.1 13.91,32.71 v1(13.91,32.05) ; R61.2 v1(15.61,29.95) R55.2
  vias: v1(17.51,37.35) v1(17.51,36.65)
LDO4P5: length 8.8
  TOP w0.15: R62.1 18.81,23.71 v1(18.81,24.15)
  TOP w0.25: R62.1 R63.1 ; C43.1 C42.1 v1(22.74,23.55) 23.22,23.07 U3.8
  L3_PWR w0.25: v1(18.81,24.15) 19.06,23.9 22.4,23.9 v1(22.74,23.55)
NTC_MPP: length 63.5
  TOP w0.15: NTC2.1 v1(36.11,19.55) ; TP_NTC_COIL1.1 R56.1 R25.1 13.65,35.7 v1(13.31,35.35) ; v1(28.21,20.03) 27.62,20.62 27.62,21.02 27.77,21.17 U3.20
  TOP w0.2: NTC1.1 v1(20.35,16.56)
  L3_PWR w0.15: v1(28.21,20.03) 28.21,19.83 28.84,19.2 32.71,19.2 33.06,19.55 v1(36.11,19.55) 36.11,18.95 37.21,17.85 37.21,14.55 35.91,13.25 24.01,13.25 21.31,15.95 20.96,15.95 v1(20.35,16.56) 20.35,18.71 19.81,19.25 18.41,19.25 15.11,22.55 15.11,27.35 13.01,29.45 13.01,33.68 13.31,33.98 v1(13.31,35.35)
SCL0_DP: length 21.3
  TOP w0.15: U3.10 23.03,22.27 22.96,22.21 v1(22.75,22.21) ; v1(28.65,31.35) TP_SCL0_DP1.1 R47.1 R9.2
  L3_PWR w0.15: v1(28.65,31.35) 28.2,30.9 25.76,30.9 25.26,31.41 23.32,31.41 22.91,30.99 22.91,30.3 21.41,28.8 21.41,26.05 23.5,23.96 23.5,22.65 23.05,22.21 v1(22.75,22.21)
SCL1: length 38.1
  TOP w0.15: R57.1 R55.1 v1(14.07,29.25) ; R58.1 v1(16.21,36.45) ; U3.21 28.32,21.87 28.51,21.69 28.51,21.21 v1(28.1,20.81)
  L3_PWR w0.15: v1(16.21,36.45) 13.31,33.55 13.31,30.01 v1(14.07,29.25) 14.87,28.45 18.55,28.45 19.01,27.99 19.01,27.25 18.86,27.1 18.31,27.1 16.91,25.69 16.91,23.35 19.26,21 20.23,21 22.27,18.96 26.26,18.96 v1(28.1,20.81)
SCL1_1: length 3.1
  TOP w0.15: R59.1 R57.2 14.95,31.7 15.31,32.05 U5.3
SCL1_2: length 1.4
  TOP w0.15: R58.2 15.91,34.51 U5.6
SCT_EN: length 4.6
  TOP w0.15: v1(48.8,29.23) 48.38,29.23 48.11,28.95 U2.2 ; v1(49.51,30.91) R20.2 R10.1
  L3_PWR w0.15: v1(49.51,30.91) 48.8,30.2 v1(48.8,29.23)
SCT_MODE: length 13.6
  TOP w0.15: R51.1 52.75,29.37 52.61,29.23 R50.2 v1(53.27,28.8)
  TOP w0.2: v1(44.11,25.05) 44.36,25.05 U2.12
  L3_PWR w0.2: v1(44.11,25.05) 49.98,25.05 51.76,26.84 51.76,27.7 52.85,28.8 v1(53.27,28.8)
SCT_SS: length 2.1
  TOP w0.2: C51.2 43.52,28.74 44.16,28.1 U2.10
SCT_VCC: length 4.7
  TOP w0.15: R51.2 v1(51.21,29.85) ; C15.1 v1(50.78,28.79)
  TOP w0.2: C15.1 49.54,28.79 49.01,28.25 49.01,27.95 48.81,27.75 U2.1
  L3_PWR w0.15: v1(50.78,28.79) 50.78,29.42 v1(51.21,29.85)
SDA0_DN: length 18.5
  TOP w0.15: R11.2 R46.1 25.59,32.77 TP_SDA0_DN1.1 v1(26.11,31.35) ; U3.9 23.13,22.67 23.01,22.79 22.75,22.79 v1(22.75,22.79)
  L3_PWR w0.15: v1(26.11,31.35) 25.76,31.71 23.2,31.71 22.61,31.12 22.61,30.5 21.04,28.93 21.04,25.92 23.2,23.76 23.2,23.24 v1(22.75,22.79)
SDA1_1: length 1.3
  TOP w0.15: R56.2 15.31,34.61 U5.1
SW: length 0.9
  TOP w0.2: R4.2 48.81,30.46
SW1: length 2.4
  TOP w0.25: U3.16 25.8,20.24 ; 25.8,20.24 25.21,19.65 ; 25.8,20.24 25.8,20.09 25.61,19.9
SW1_RC: length 1
  TOP w0.15: C27.2 R31.1
SW2: length 1.6
  TOP w0.25: 26.6,20.26 26.71,20.15 ; 26.6,20.26 26.6,19.86 ; 26.6,20.26 U3.18
SW2_RC: length 1
  TOP w0.15: C21.1 30.43,19.05 30.45,19.04 R24.2
SW_CTX2: length 12.3
  TOP w0.15: D8.2 TP_CTX2.1 17.07,24.46 R63.2 17.07,23.1 17.11,23.05 17.75,23.05 17.95,22.85 R65.1 18.31,22.2 18.31,21.74 19.38,20.67 23.88,20.67 24,20.8 U3.13
SW_CTX3: length 11.3
  TOP w0.15: D6.2 TP_CTX1.1 19.85,24.46 R62.2 19.85,23.2 19.71,23.05 19.07,23.05 18.97,22.95 R64.1 18.61,22.2 18.61,21.87 19.5,20.97 23.63,20.97 23.82,21.17 U3.12
SW_RC: length 1.6
  TOP w0.2: C1.2 50.9,29.41 50.75,29.41 R4.1
SWITCH_G1: length 26.9
  TOP w0.15: C39.2 v1(28.81,14.91) R38.2 ; D8.1 v1(16.81,27.55) ; 32.91,16.83 v1(32.21,16.83)
  L3_PWR w0.15: v1(16.81,27.55) 16.81,27.25 16.61,27.05 16.61,23.16 19.2,20.57 20.21,20.57 25.87,14.91 v1(28.81,14.91) 30.73,16.83 v1(32.21,16.83)
SWITCH_G2: length 30.5
  TOP w0.15: C26.2 v1(30.52,14.3) R27.2 ; D6.1 v1(18.51,27.55) ; Q2.4 v1(32.91,15)
  L3_PWR w0.15: v1(18.51,27.55) 18.06,28.01 16.62,28.01 16.31,27.69 16.31,23.03 19.08,20.27 20.09,20.27 26.05,14.3 v1(30.52,14.3) 31.22,15 v1(32.91,15)
TX_BST1: length 3.9
  TOP w0.15: C36.1 26.41,17.41 26.2,17.63 U3.17
TX_BST2: length 3.6
  TOP w0.15: U3.19 27,20.55 28.67,18.88 29.03,18.88 C25.1
VCOIL: length 33.2
  TOP w0.25: D7.2 17.41,17.35 17.92,17.86 v1(17.92,18.4) R34.2
  L3_PWR w0.3: v1(17.92,18.4) 17.92,17.59 24.75,10.75 v1(44.71,10.75)
VPA: length 21.9
  TOP w0.2: v1(48.88,22.95) R52.1 47.82,22.95 47.82,22.96 C14.1
  TOP w0.25: 25.11,24.95 25.4,24.66 25.4,24.46 ; 25.01,24.85 25.4,24.46 ; 25.4,24.46 U3.5
  L3_PWR w0.25: v1(48.88,22.95) 41.61,22.95 36.91,27.65 v1(32.81,27.65)
  vias: v1(22.71,28.45) v1(22.71,27.85) v1(22.71,27.25) v1(23.31,28.45) v1(23.31,27.85) v1(23.81,28.15) v1(30.14,28.35) v1(30.15,27.64) v1(30.14,26.88) v1(30.84,28.35) v1(30.85,27.64) v1(30.84,26.88)
XTAL_IN: length 7.2
  TOP w0.15: Y1.3 33.66,22.2 33.39,22.47 30.97,22.47 C37.2 29.98,21.92 29.87,22.03 R39.2 29.2,22.03 28.96,22.27 U3.22
XTAL_OUT: length 4.6
  TOP w0.15: Y1.1 31.42,23.03 C41.2 29.98,23.03 29.87,22.92 R39.1 29.2,22.92 28.96,22.67 U3.23

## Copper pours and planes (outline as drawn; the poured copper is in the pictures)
GND_IN on TOP, BOTTOM, L2_GND, L3_PWR: outline of 105 points within 8.22,2.93 59.6,53.53
GND_POWER on TOP: outline of 159 points within 9.83,4.55 57.99,48.59 ; 1 cut-out
GND_POWER on BOTTOM: outline of 107 points within 10.22,5.09 57.37,48.59
GND_POWER on L2_GND: outline of 138 points within 10.22,5.09 57.37,48.59
GND_POWER on L3_PWR: outline of 154 points within 10.22,5.09 57.37,48.59
GND_SIG on TOP: outline of 136 points within 12.66,12.5 37.08,39.5
GND_SIG on TOP: 19.71,38.85 21.61,38.85 21.91,38.55 21.91,35.05 21.61,34.75 19.41,34.75 19.11,35.05 19.11,35.55 19.41,35.85 19.41,38.55
GND_SIG on L2_GND: 26.11,9.1 16.31,18.9 14.71,18.9 14.16,19.46 14.16,26.66 12.66,28.16 12.66,35.75 16.41,39.5 21.51,39.5 21.86,39.15 21.86,34.96 21.71,34.8 18.71,34.8 18.16,34.26 18.16,30.05 19.01,29.2 20.81,29.2 21.86,28.15 21.86,25.25 22.91,24.2 24.31,24.2 24.46,24.05 24.46,22.45 24.81,22.1 27.81,22.1 28.96,23.25 28.96,24.35 29.81,25.2 34.31,25.2 35.06,24.45 35.06,23.25 36.76,21.55 36.76,19.65 38.21,18.2 47.31,18.2 48.36,17.15 48.36,12.46 47.21,11.3 45.51,11.3 44.41,10.2 38.01,10.2 37.38,9.58 33.76,9.25 30.14,9.63 29.51,9.55 29.05,9.1
GND_SIG on L3_PWR: 29.51,9.55 29.05,9.1 26.11,9.1 16.31,18.9 14.71,18.9 14.16,19.46 14.16,26.66 12.66,28.16 12.66,35.75 16.41,39.5 21.51,39.5 21.86,39.15 21.86,34.96 21.71,34.8 18.71,34.8 18.16,34.26 18.16,30.05 19.01,29.2 20.81,29.2 21.86,28.15 21.86,25.25 22.91,24.2 24.31,24.2 24.46,24.05 24.46,22.45 24.81,22.1 27.81,22.1 28.96,23.25 28.96,24.35 29.81,25.2 34.31,25.2 35.06,24.45 35.06,23.25 36.76,21.55 36.76,19.65 38.21,18.2 47.31,18.2 48.36,17.15 48.36,12.46 47.21,11.3 45.51,11.3 44.41,10.2 38.01,10.2 37.38,9.58 33.76,9.25 30.14,9.63 ; 6 cut-outs
VBUS on TOP: 21.91,34.25 21.91,33.15 21.71,32.95 20.61,32.95 20.01,32.35 18.91,32.35 18.61,32.65 18.61,33.95 19.01,34.35 21.81,34.35
VBUS on TOP: 41.31,45.58 38.28,45.58 38.13,45.43 38.13,41.3 38.12,41.29 38.12,38.3 37.37,37.55 37.37,32.14 37.96,31.55 42.86,31.55 43.61,32.3 43.61,36.2 41.51,38.3 41.51,45.38
VBUS on L3_PWR: 19.91,34.15 19.91,33.15 20.21,32.85 22.21,32.85 22.41,33.05 27.71,33.05 28.51,32.25 38.01,32.25 38.61,32.85 38.61,34.85 38.41,35.05 22.71,35.05 21.91,34.25 20.01,34.25
LDO3P3 on TOP: 18.71,37.65 18.71,35.15 18.31,34.75 17.71,34.75 17.31,35.15 17.31,37.75 17.41,37.85 18.51,37.85
LDO3P3 on L3_PWR: 17.41,38.25 18.01,38.25 18.21,38.05 18.21,32.15 15.81,29.75 15.41,29.75 13.61,31.55 13.61,32.15 13.81,32.35 14.01,32.35 15.41,30.95 15.91,30.95 17.31,32.35 17.31,38.15
SW on TOP: 49.01,35.25 48.81,35.45 45.41,35.45 45.11,35.15 45.11,29.6 45.46,29.25 45.46,28.3 47.26,28.3 47.26,29.15 47.71,29.6 47.71,30.15 47.86,30.3 48.76,30.3 49.01,30.55
SW1 on TOP: 23.86,18.11 24.06,18.3 24.58,18.3 24.83,18.56 24.83,19.34 25.01,19.52 25.01,19.81 25.67,20.46 25.67,21.61 25.71,21.65 25.81,21.65 25.92,21.54 25.92,20.52 25.96,20.48 25.96,18.71 25.83,18.58 25.83,17.49 25.83,17.49 25.83,16.58 26.31,16.1 26.31,13.15 29.61,9.85 29.61,9.6 29.2,9.32 28.97,8.88 28.41,6.45 26.71,6.45 24.1,7.23 23.86,7.47
SW2 on TOP: 29.11,18.05 32.91,18.05 33.26,17.7 33.26,14.7 33.66,14.3 37.16,14.3 37.26,14.2 37.26,13 37.11,12.85 31.31,12.85 31.06,13.1 31.06,15.35 30.86,15.55 27.61,15.55 26.94,16.22 26.94,17.33 26.41,17.86 26.41,20.68 26.47,20.74 26.47,21.61 26.51,21.65 26.71,21.65 26.72,21.64 26.72,20.44
SW_D1 on TOP: 46.26,16.15 46.26,14.65 46.41,14.5 48.26,14.5 48.41,14.65 48.41,16.8 47.21,18 33.96,18 33.81,17.85 33.81,16.8 33.96,16.65 45.76,16.65
SW_D2 on TOP: 33.96,16.4 45.66,16.4 46.01,16.05 46.01,14.6 45.91,14.5 33.96,14.5 33.81,14.65 33.81,16.25
VCOIL on TOP: 39.34,6.76 38.85,8.88 38.42,9.5 37.68,9.63 35.45,9.32 33.2,9.27 33.01,9.45 33.01,12.1 33.31,12.4 37.56,12.4 38.66,13.5 47.81,13.5 48.11,13.2 48.11,11.25 47.91,11.05 47.1,11.05 43.81,7.76 41.65,6.95
VPA on TOP: 25.31,22.65 25.31,23.15 25.21,23.25 25.21,24.55 25.11,24.65 24.41,24.65 22.51,26.55 22.51,28.65 22.61,28.75 23.51,28.75 24.01,28.25 24.01,27.35 25.51,25.85 25.51,25.4 25.61,25.3 25.61,23.45 25.51,23.35 25.51,22.65
VPA on TOP: 38.41,22.55 34.71,26.25 29.31,26.25 28.11,25.05 28.11,24.55 27.16,23.6 27.16,22.7 27.06,22.6 26.91,22.6 26.86,22.65 26.86,25.6 29.91,28.65 35.61,28.65 36.01,28.25 37.31,28.25 37.71,27.85 37.71,26.25 38.91,25.05 43.81,25.05 44.06,24.8 45.21,24.8 45.41,25 45.41,25.7 46.61,25.7 46.76,25.55 46.76,22.8 46.51,22.55
VPA on L3_PWR: 22.61,28.65 30.91,28.65 31.11,28.45 31.11,26.75 31.01,26.65 22.81,26.65 22.51,26.95 22.51,28.55

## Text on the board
Ref Des/Silkscreen Bottom: WB8118_MPP_Tx_V0.5
Ref Des/Silkscreen Top: NTC | GND | CC2 | GND_POWER | DN | DP | CC1 | VPA | VBUS | PWM | CTX2 | CTX1
DIMENSION: dia 52,8\U+00B10,1 | 0,6%%P0.05
NCLEGEND-1-4: FIGURE | SIZE | 0.15 | 0.2032 | 0.5 | DRILL CHART: TOP to BOTTOM | ALL UNITS ARE IN MILLIMETERS | TOLERANCE | +0.0/-0.0 | +0.0762/-0.0762 | PLATED | NON-PLATED | QTY | 2 | 495 | 30
